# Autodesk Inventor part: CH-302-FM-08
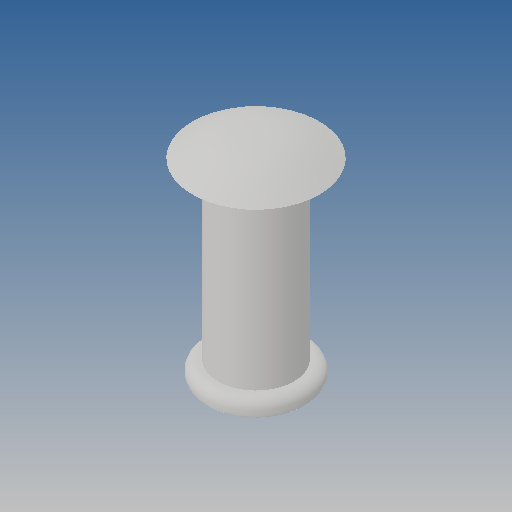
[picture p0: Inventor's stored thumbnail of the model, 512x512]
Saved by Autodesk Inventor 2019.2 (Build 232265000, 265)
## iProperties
Created: 2013-03
Part Number: CH-302-FM-08
Material: Ogólny
Document SubType Name: Modeling
Designer: CADENGINEERING4
Density: 1 g/cm^3
Appearance: Domyślna
Author: CADENGINEERING4
Revision Number: ÈÎºÎ
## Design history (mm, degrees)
feature "Ô²½Ç2"
node "Bryła1"
